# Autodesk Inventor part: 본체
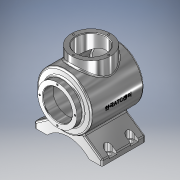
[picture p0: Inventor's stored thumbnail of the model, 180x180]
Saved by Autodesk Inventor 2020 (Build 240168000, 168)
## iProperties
Created: 2023-12
Part Number: 본체
Material: 알루미늄 6061
Document SubType Name: Modeling
Designer: 1강의실14
Density: 2.7 g/cm^3
Appearance: 알루미늄 - 평지
Mass: 1296.71 g
Surface Area: 1060.44 cm^2
Volume: 480.264 cm^3
Author: 1강의실14
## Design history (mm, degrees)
sketch "스케치1"
  geometry: L1 (0, 0)-(0, 108); L2 (0, 108)-(50, 108); L3 (50, 108)-(50, 0); L4 (0, 108)-(0, 0); L5 (50, 108)-(50, 11.664); A1 r 113 centre (0, 113) between (0, 0) and (50, 11.664)
  constraints: 10 end point, 2 collinear, 2 point on circle, 2 point on line, 2 vertical, 2 vertical alignment, 1 centre point, 1 horizontal, 1 horizontal alignment
  dimensions: "d0" = 100 diameter of L2.end L1; "d1" = 108 distance of L2.end L3.end; "d2" = 113 radius of A1; "d3" = 108 distance of L1.start L1.end
revolve "회전1" sketch "스케치1" stored, may be unused: angle "d4" = 90 deg
feature "쉘1" dims "d5" = 7
sketch "스케치2"
  geometry: C1 r 36 at (0, 0); 1 further point
  constraints: 1 centre point, 1 coincident
  dimensions: "d6" = 72 diameter of C1
extrude "돌출1" join sketch "스케치2" distance "d7" = 12; taper "d8" = 0 deg
sketch "스케치3"
  geometry: C1 r 36 at (0, 0) reference; 2 further points
  constraints: 1 coincident
hole "구멍1" sketch "스케치3" at (0, 0) diameter "d9" = 54; stored, may be unused: countersink angle "d13" = 90 deg, drill point angle "d15" = 0 deg; dims "d10" = 6, "d11" = 50, "d12" = 15, "d14" = 19
node "작업 평면2"
  node "작업 평면1"
sketch "스케치4"
  geometry: L1 (0, 0)-(0, -77); L2 (0, -77)-(62, -77); L3 (62, -77)-(62, -67); L4 (62, -67)-(26.694, -42.278); L5 (0, -77)-(0, -50); L6 (0, -77)-(38.5, -77); L7 (0, -77)-(0, -60); L8 (0, -60)-(0, -50); L9 (38.5, -77)-(62, -77); L10 (-62, -67)-(-26.694, -42.278); L11 (0, -77)-(-62, -77); L12 (-62, -77)-(-62, -67); L13 (-38.5, -77)-(-62, -77); A1 r 50 centre (0, 0) between (26.694, -42.278) and (0, -50) reference; A2 r 52.096 centre (0, -112.096) between (38.5, -77) and (0, -60); A3 r 52.096 centre (0, -112.096) between (0, -60) and (-38.5, -77); 1 further point
  constraints: 26 end point, 6 point on circle, 5 point on line, 4 symmetric about line, 2 centre point, 2 collinear, 2 vertical, 1 perpendicular, 1 other
  dimensions: "d18" = 77 distance of L1.start L1.end; "d19" = 62 distance of L1.end L2.end; "d20" = 10 distance of L2.end L3.end; "d21" = 55 deg angle of L3 L4; "d22" = 38.5 distance of L1.end L6.end; "d23" = 17 distance of L1.end L7.end
extrude "돌출2" join sketch "스케치4" distance "d24" = 80; taper "d25" = 0 deg
node "작업 평면4"
sketch "스케치6" dims "d47" = 10
  geometry: L1 (-62, 100)-(-62, 20) reference; L2 (-62, 20)-(-62, 40); L3 (-62, 40)-(-54, 40); L4 (-54, 47)-(-62, 47); L5 (-54, 33)-(-62, 33); L6 (-62, 80)-(-54, 80); L7 (-54, 87)-(-62, 87); L8 (-54, 73)-(-62, 73); L9 (0, -24)-(0, 144) reference; L10 (54, 73)-(62, 73); L11 (62, 80)-(54, 80); L12 (54, 87)-(62, 87); L13 (54, 47)-(62, 47); L14 (62, 40)-(54, 40); L15 (54, 33)-(62, 33); L16 (-62, 87)-(-62, 73); L17 (-62, 47)-(-62, 33); L18 (62, 87)-(62, 73); L19 (62, 100)-(62, 20) reference; L20 (62, 47)-(62, 33); A1 r 7 centre (-54, 40) between (-54, 33) and (-54, 47); A2 r 7 centre (-54, 80) between (-54, 73) and (-54, 87); A3 r 7 centre (54, 80) between (54, 87) and (54, 73); A4 r 7 centre (54, 40) between (54, 47) and (54, 33); 1 further point
  constraints: 34 end point, 14 symmetric about line, 8 point on circle, 4 centre point, 4 coincident, 4 collinear, 3 point on line, 2 perpendicular, 2 tangent, 1 horizontal, 1 vertical, 13 other
  dimensions: "d39" = 20 distance of L1.end L2.end; "d40" = 8 horizontal distance of L1.end L3.end; "d41" = 14 diameter of A1; "d44" = 40 distance of L3.end L6.end
extrude "돌출3" cut sketch "스케치6" stored distance "d49" = 80; taper "d50" = 0 deg
sketch "스케치7"
  geometry: A1 r 7 centre (54, -80) between (54, -73) and (54, -87) reference; A2 r 7 centre (54, -40) between (54, -33) and (54, -47) reference; A3 r 7 centre (-54, -80) between (-54, -87) and (-54, -73) reference; A4 r 7 centre (-54, -40) between (-54, -47) and (-54, -33) reference; 5 further points
  constraints: 4 coincident
hole "구멍2" sketch "스케치7" at (54, -80), (54, -40), (-54, -80), (-54, -40) diameter "d51" = 9; stored, may be unused: countersink angle "d55" = 90 deg, drill point angle "d57" = 0 deg; dims "d52" = 6, "d53" = 50, "d54" = 15, "d56" = 19
node "작업 평면5"
sketch "스케치8"
  geometry: L1 (-27, 120)-(27, 120) reference; L2 (0, 120)-(0, 58); C1 r 36 at (0, 58); 1 further point
  constraints: 2 end point, 1 centre point, 1 coincident, 1 midpoint, 1 vertical
  dimensions: "d59" = 62 distance of L2.start L2.end; "d60" = 72 diameter of C1
extrude "돌출4" join sketch "스케치8" stored distance "d61" = 80; taper "d62" = 0 deg
sketch "스케치10"
  geometry: C1 r 36 at (0, 0) reference; 2 further points
  constraints: 1 coincident
hole "구멍3" sketch "스케치10" at (0, 0) diameter "d65" = 54; stored, may be unused: countersink angle "d69" = 90 deg, drill point angle "d71" = 0 deg; dims "d66" = 6, "d67" = 50, "d68" = 15, "d70" = 67.7454
fillet "모깎기1" dims "d72" = 3
fillet "모깎기2" dims "d73" = 3
chamfer "모따기1" distance "d74" = 1; stored, may be unused: second distance "d75" = 2, angle "d76" = 45 deg
chamfer "모따기2" distance "d77" = 1; stored, may be unused: second distance "d78" = 2, angle "d79" = 45 deg
fillet "모깎기3" dims "d80" = 3
fillet "모깎기4" dims "d81" = 3
fillet "모깎기5" dims "d82" = 3
sketch "스케치11" dims "d83" = 65
  geometry: L1 (0, 0)-(0, 32.5); 1 further point
  constraints: 2 end point, 1 coincident, 1 vertical, 1 vertical alignment, 2 other
hole "구멍4" sketch "스케치11" at (0, 32.5) diameter "d84" = 3.242; stored, may be unused: countersink angle "d88" = 90 deg, drill point angle "d90" = 118 deg; dims "d85" = 8, "d86" = 50, "d87" = 15, "d89" = 10
sketch "스케치12" dims "d94" = 65
  geometry: L1 (0, 0)-(0, 32.5); C1 r 36 at (0, 0) reference; 2 further points
  constraints: 2 end point, 1 vertical, 1 vertical alignment, 3 other
hole "구멍5" sketch "스케치12" at (0, 32.5) diameter "d95" = 3.242; stored, may be unused: countersink angle "d99" = 90 deg, drill point angle "d101" = 118 deg; dims "d96" = 8, "d97" = 50, "d98" = 15, "d100" = 10
node "작업 평면6"
sketch "스케치13"
  geometry: L1 (36, 120)-(-36, 120) reference; L2 (65, 22)-(65, 94) reference; L3 (65, 58)-(-77, 58); L4 (-77, 100)-(-77, 20) reference; 2 further points
  constraints: 2 end point, 1 horizontal, 1 horizontal alignment, 1 midpoint, 1 point on line, 1 vertical alignment, 1 other
  dimensions: "d106" = 62 vertical distance of L1.start L3.start (derived)
feature "엠보싱1" sketch "스케치13" dims "d12" = 15, "d107" = 0.5, "d108" = 0
node "솔리드1"
pattern_circular "원형 패턴1" dims angle "d92" = 360 deg
pattern_circular "원형 패턴2" dims angle "d103" = 360 deg
feature "A9D066F2-1C7D-4E18-AEED-F7BC21143FA4" dims "d9" = 54, "d10" = 6, "d11" = 50, "d12" = 15, "d13" = 90 deg, "d14" = 19, "d15" = 0
other parameters: "d38" = -71, "d58" = 65
